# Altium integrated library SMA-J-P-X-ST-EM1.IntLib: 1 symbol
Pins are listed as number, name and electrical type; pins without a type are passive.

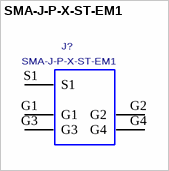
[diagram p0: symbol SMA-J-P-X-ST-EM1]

## SMA-J-P-X-ST-EM1
designator J?
SMA STRAIGHT, EDGE MOUNT JACK- 50 OHM; MANUFACTURER: SAMTEC
footprint SMA-J-P-X-ST-EM1
pins: G1, G2, G3, G4, S1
